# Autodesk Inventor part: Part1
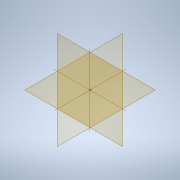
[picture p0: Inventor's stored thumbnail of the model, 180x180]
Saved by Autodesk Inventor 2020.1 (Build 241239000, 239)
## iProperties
Created: 2019-10
Part Number: Part1
Material: Generic
Document SubType Name: Modeling
Designer: Synergysoft Dell02
Density: 1 g/cm^3
Appearance: Default
Author: Synergysoft Dell02
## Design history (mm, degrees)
